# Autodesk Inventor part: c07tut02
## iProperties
Shininess: 77.0
Length Units: 11269
Angle Units: 11279
Time Units: 11290
Mass Units: 11283
Length Display Precision: 3
Angle Display Precision: 2
Created: 2002-01
Part Number: c07tut02
Document SubType Name: Modeling
Designer: ***
Density: 1 g/cm^3
Density: 0.0
Volumn: 0.0
Area: 0.0
PropertySet Name: Model Information
Control State: 0
Master: False
Checked Out: False
Author: ***
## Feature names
1. Extrusion1
2. Extrusion2
3. Extrusion3
4. Chamfer1
